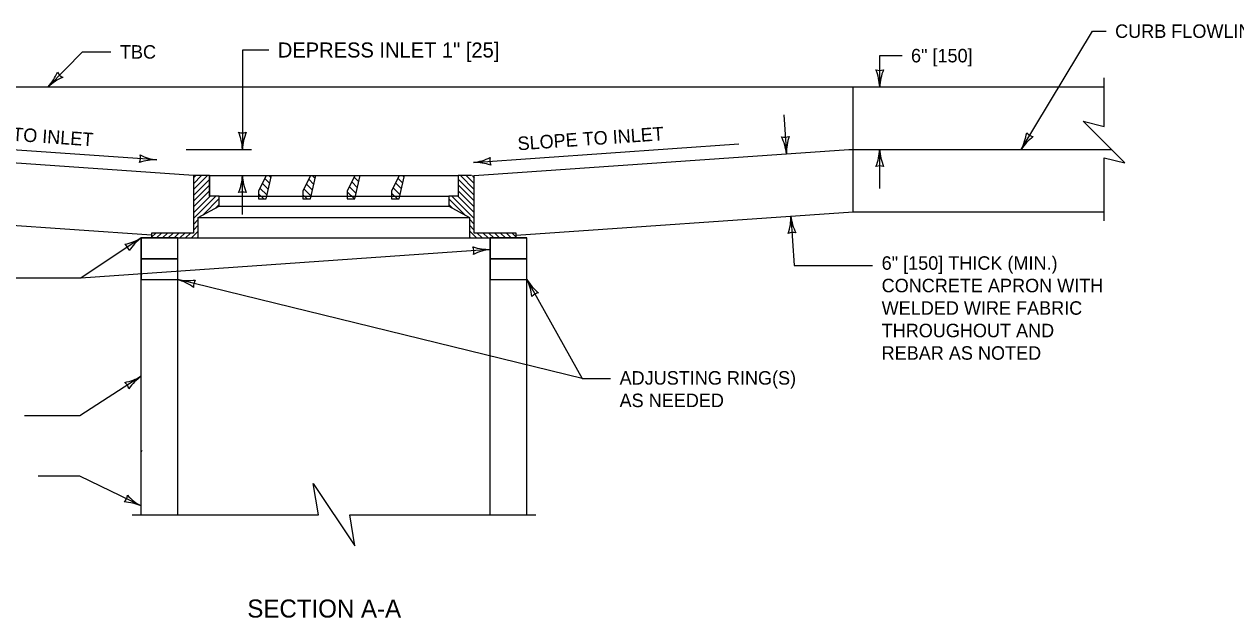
# Model space of a CAD drawing. Extents: x 49991.4 to 50048.3, y 49987.6 to 50018.3.
# Drawn here: x 50007.22 to 50012.6, y 49991.19 to 49993.83 of the extents above; entities that cross this region are included whole.
import ezdxf

# ---------------------------------------------------------------- set-up
doc = ezdxf.new("R2010")
doc.units = 0
for name, color, linetype in [('Level 1', 7, 'Continuous'), ('Level 2', 7, 'Continuous'), ('Level 3', 7, 'Continuous'), ('Level 4', 7, 'Continuous'), ('Level 6', 7, 'Continuous')]:
    doc.layers.add(name, color=color, linetype=linetype)

msp = doc.modelspace()

# ---------------------------------------------------------------- linework, layer by layer
at = {"layer": 'Level 1'}
for p, q in [((50006.2842, 49993.5547), (50010.9017, 49993.5547)), ((50010.9017, 49993.5547), (50012.0159, 49993.5547)), ((50010.9017, 49992.9997), (50010.9017, 49993.5547)), ((50007.9687, 49993.1608), (50006.3036, 49993.2772)), ((50009.2173, 49993.1608), (50010.8823, 49993.2772)), ((50010.8823, 49993.2772), (50012.048, 49993.2772)), ((50008.0399, 49993.1608), (50007.9687, 49993.1608)), ((50007.9687, 49993.1608), (50007.9687, 49992.9052)), ((50007.9687, 49993.1501), (50007.9794, 49993.1608)), ((50007.9687, 49993.1242), (50008.0052, 49993.1608)), ((50007.9687, 49993.0984), (50008.0311, 49993.1608)), ((50008.0399, 49993.1608), (50009.1461, 49993.1608)), ((50008.0399, 49993.1608), (50008.0399, 49993.0695)), ((50008.0399, 49993.0695), (50008.0399, 49993.1608)), ((50008.3042, 49993.1608), (50008.3137, 49993.1512)), ((50008.4965, 49993.1608), (50008.5099, 49993.1474)), ((50008.6831, 49993.1534), (50008.7037, 49993.1328)), ((50008.7075, 49993.1608), (50008.7095, 49993.1588)), ((50008.8981, 49993.1608), (50008.9054, 49993.1535)), ((50009.1461, 49993.1608), (50009.1461, 49993.0695)), ((50009.2045, 49993.1608), (50009.1461, 49993.1608)), ((50009.1461, 49993.1608), (50009.1461, 49993.0695)), ((50009.1557, 49993.1608), (50009.2173, 49993.0993)), ((50009.1815, 49993.1608), (50009.2173, 49993.1251)), ((50009.2073, 49993.1608), (50009.2173, 49993.1509)), ((50009.2173, 49992.9052), (50009.2173, 49993.1608)), ((50007.9687, 49993.0726), (50008.0399, 49993.1438)), ((50007.9687, 49993.0468), (50008.0399, 49993.118)), ((50008.2647, 49993.1048), (50008.2964, 49993.0731)), ((50008.2753, 49993.126), (50008.3022, 49993.0991)), ((50008.2859, 49993.1472), (50008.308, 49993.1252)), ((50008.4602, 49993.1017), (50008.4926, 49993.0693)), ((50008.4708, 49993.1229), (50008.4984, 49993.0953)), ((50008.4814, 49993.1441), (50008.5042, 49993.1214)), ((50008.6619, 49993.111), (50008.6922, 49993.0807)), ((50008.6725, 49993.1322), (50008.698, 49993.1067)), ((50008.8568, 49993.1066), (50008.888, 49993.0754)), ((50008.8674, 49993.1278), (50008.8938, 49993.1014)), ((50008.878, 49993.1491), (50008.8996, 49993.1274)), ((50009.1461, 49993.1446), (50009.2173, 49993.0734)), ((50009.1461, 49993.1188), (50009.2173, 49993.0476)), ((50007.9687, 49993.021), (50008.0399, 49993.0922)), ((50007.9687, 49992.9952), (50008.0431, 49993.0695)), ((50007.9687, 49992.9694), (50008.0689, 49993.0695)), ((50008.0101, 49992.9849), (50008.0837, 49993.0585)), ((50008.0837, 49993.0695), (50008.0399, 49993.0695)), ((50008.0837, 49993.0239), (50008.0837, 49993.0695)), ((50008.2579, 49993.0798), (50008.2812, 49993.0565)), ((50008.455, 49993.0751), (50008.4736, 49993.0565)), ((50008.652, 49993.089), (50008.6846, 49993.0565)), ((50008.652, 49993.0572), (50008.6528, 49993.0565)), ((50008.8491, 49993.0825), (50008.8751, 49993.0565)), ((50009.1461, 49993.0695), (50009.1041, 49993.0695)), ((50009.1041, 49993.0695), (50009.1041, 49993.0239)), ((50009.1041, 49993.0575), (50009.1772, 49992.9844)), ((50009.1179, 49993.0695), (50009.2173, 49992.9702)), ((50009.1437, 49993.0695), (50009.2173, 49992.996)), ((50009.1461, 49993.093), (50009.2173, 49993.0218)), ((50007.7825, 49992.8949), (50006.2842, 49992.9997)), ((50007.9906, 49992.9746), (50008.0837, 49993.0239)), ((50008.0649, 49993.014), (50008.0837, 49993.0327)), ((50009.1041, 49993.0317), (50009.1211, 49993.0147)), ((50009.1041, 49993.0239), (50009.1953, 49992.9746)), ((50009.4034, 49992.8949), (50010.9017, 49992.9997)), ((50010.9017, 49992.9997), (50012.0159, 49992.9997)), ((50007.9687, 49992.9435), (50007.9906, 49992.9654)), ((50007.9687, 49992.9177), (50007.9906, 49992.9396)), ((50007.9906, 49992.9746), (50009.1953, 49992.9746)), ((50007.9906, 49992.8833), (50007.9906, 49992.9746)), ((50009.1953, 49992.9746), (50009.1953, 49992.8833)), ((50009.1953, 49992.9663), (50009.2173, 49992.9444)), ((50009.1953, 49992.9405), (50009.2173, 49992.9185)), ((50007.7369, 49991.653), (50007.7369, 49992.8833)), ((50007.7369, 49992.8833), (50007.8993, 49992.8833)), ((50007.7825, 49992.9034), (50007.7843, 49992.9052)), ((50007.9687, 49992.9052), (50007.7825, 49992.9052)), ((50007.7825, 49992.9052), (50007.7825, 49992.8833)), ((50007.7825, 49992.8864), (50007.8013, 49992.9052)), ((50007.7825, 49992.8833), (50007.9906, 49992.8833)), ((50007.8052, 49992.8833), (50007.8271, 49992.9052)), ((50007.831, 49992.8833), (50007.853, 49992.9052)), ((50007.8569, 49992.8833), (50007.8788, 49992.9052)), ((50007.8827, 49992.8833), (50007.9046, 49992.9052)), ((50007.8993, 49991.653), (50007.8993, 49992.8833)), ((50007.9085, 49992.8833), (50007.9304, 49992.9052)), ((50007.9343, 49992.8833), (50007.9562, 49992.9052)), ((50007.9601, 49992.8833), (50007.9906, 49992.9138)), ((50007.9859, 49992.8833), (50007.9906, 49992.888)), ((50007.9906, 49992.8833), (50009.1953, 49992.8833)), ((50009.1953, 49992.9146), (50009.2267, 49992.8833)), ((50009.1953, 49992.8888), (50009.2008, 49992.8833)), ((50009.1953, 49992.8833), (50009.4034, 49992.8833)), ((50009.4034, 49992.9052), (50009.2173, 49992.9052)), ((50009.2306, 49992.9052), (50009.2525, 49992.8833)), ((50009.2564, 49992.9052), (50009.2783, 49992.8833)), ((50009.2822, 49992.9052), (50009.3041, 49992.8833)), ((50009.2884, 49992.8833), (50009.4509, 49992.8833)), ((50009.2884, 49991.653), (50009.2884, 49992.8833)), ((50009.308, 49992.9052), (50009.3299, 49992.8833)), ((50009.3338, 49992.9052), (50009.3557, 49992.8833)), ((50009.3596, 49992.9052), (50009.3815, 49992.8833)), ((50009.3855, 49992.9052), (50009.4034, 49992.8872)), ((50009.4034, 49992.8833), (50009.4034, 49992.9052)), ((50009.4509, 49991.653), (50009.4509, 49992.8833)), ((50007.7369, 49991.9305), (50007.7405, 49991.9396))]:
    msp.add_line(p, q, dxfattribs=at)
for points in [[(50008.2927, 49993.1608), (50008.2579, 49993.0912), (50008.2579, 49993.0565), (50008.2927, 49993.0565), (50008.3159, 49993.1608)], [(50008.4897, 49993.1608), (50008.455, 49993.0912), (50008.455, 49993.0565), (50008.4897, 49993.0565), (50008.5129, 49993.1608)], [(50008.6868, 49993.1608), (50008.652, 49993.0912), (50008.652, 49993.0565), (50008.6868, 49993.0565), (50008.71, 49993.1608)], [(50008.8838, 49993.1608), (50008.8491, 49993.0912), (50008.8491, 49993.0565), (50008.8838, 49993.0565), (50008.907, 49993.1608)]]:
    msp.add_lwpolyline(points, dxfattribs=at)
for points in [[(50007.8993, 49992.8833), (50007.7369, 49992.8833), (50007.7369, 49992.7906), (50007.8993, 49992.7906)], [(50009.4509, 49992.7906), (50009.4509, 49992.8833), (50009.2884, 49992.8833), (50009.2884, 49992.7906)], [(50007.8993, 49992.7906), (50007.7369, 49992.7906), (50007.7369, 49992.6979), (50007.8993, 49992.6979)], [(50009.4509, 49992.6979), (50009.4509, 49992.7906), (50009.2884, 49992.7906), (50009.2884, 49992.6979)]]:
    msp.add_lwpolyline(points, close=True, dxfattribs=at)
at = {"layer": 'Level 3'}
for p, q in [((50011.6473, 49993.2772), (50011.9651, 49993.8026)), ((50011.9651, 49993.8026), (50012.0253, 49993.8026)), ((50007.3229, 49993.5547), (50007.4753, 49993.7104)), ((50008.304, 49993.7188), (50008.1865, 49993.7188)), ((50008.1865, 49993.7187), (50008.1865, 49993.2772)), ((50011.019, 49993.5547), (50011.019, 49993.6938)), ((50010.5927, 49993.4308), (50010.6048, 49993.2578)), ((50007.8062, 49993.2303), (50006.7304, 49993.3055)), ((50007.9363, 49993.2772), (50008.2265, 49993.2772)), ((50009.2132, 49993.2186), (50010.3931, 49993.3011)), ((50011.019, 49993.1038), (50011.019, 49993.2772)), ((50008.1865, 49992.9874), (50008.1865, 49993.1608)), ((50010.6242, 49992.9803), (50010.6395, 49992.7613)), ((50007.7369, 49992.8833), (50007.468, 49992.7051)), ((50009.2884, 49992.8323), (50007.468, 49992.7051)), ((50010.6395, 49992.7613), (50010.9876, 49992.7613)), ((50007.468, 49992.7051), (50006.8881, 49992.7051)), ((50009.696, 49992.2578), (50007.8993, 49992.6979)), ((50009.4509, 49992.6979), (50009.696, 49992.2578)), ((50007.7369, 49992.2682), (50007.4635, 49992.0926)), ((50009.696, 49992.2578), (50009.8229, 49992.2578)), ((50007.4635, 49992.0926), (50007.2186, 49992.0926)), ((50007.4635, 49991.824), (50007.2786, 49991.824)), ((50007.7369, 49991.6916), (50007.4635, 49991.824))]:
    msp.add_line(p, q, dxfattribs=at)
for points in [[(50007.4753, 49993.7104), (50007.6022, 49993.7104), (50007.6022, 49993.7104)], [(50011.019, 49993.6938), (50011.1181, 49993.6938), (50011.1181, 49993.6938)]]:
    msp.add_lwpolyline(points, dxfattribs=at)
for centre, radius, start, end in [((50007.1486, 49993.7093), 0.233, 318.4551, 337.705), ((50007.4753, 49993.3928), 0.2223, 113.0838, 133.2673), ((50007.4126, 49993.6464), 0.0548, 207.7666, 243.489), ((50011.019, 49993.6829), 0.0548, 252.1388, 287.8612), ((50010.7863, 49993.5432), 0.233, 2.8273, 22.0772), ((50011.2411, 49993.5456), 0.2223, 157.456, 177.6395), ((50008.1865, 49993.4054), 0.0548, 252.1388, 287.8612), ((50007.9538, 49993.2657), 0.233, 2.8273, 22.0772), ((50008.4086, 49993.2681), 0.2223, 157.456, 177.6395), ((50010.5959, 49993.3857), 0.0548, 256.1388, 291.8612), ((50010.3735, 49993.2301), 0.233, 6.8273, 26.0772), ((50010.827, 49993.2642), 0.2223, 161.456, 181.6395), ((50011.4423, 49993.3878), 0.233, 331.6545, 350.9044), ((50011.8326, 49993.1544), 0.2223, 126.2832, 146.4667), ((50011.7137, 49993.3869), 0.0548, 220.966, 256.6884), ((50010.7968, 49993.2864), 0.2223, 337.456, 357.6395), ((50011.2517, 49993.2887), 0.233, 182.8273, 202.0772), ((50007.6783, 49993.2392), 0.0548, 338.1388, 13.8612), ((50007.8014, 49992.9973), 0.233, 88.8273, 108.0772), ((50007.8308, 49993.4512), 0.2223, 243.456, 263.6395), ((50009.1855, 49993.45), 0.233, 276.8273, 296.0772), ((50009.2196, 49992.9964), 0.2223, 71.456, 91.6395), ((50009.3411, 49993.2276), 0.0548, 166.1388, 201.8612), ((50007.9644, 49993.1699), 0.2223, 337.456, 357.6395), ((50008.4192, 49993.1723), 0.233, 182.8273, 202.0772), ((50011.019, 49993.149), 0.0548, 72.1388, 107.8612), ((50008.1865, 49993.0326), 0.0548, 72.1388, 107.8612), ((50010.402, 49992.9739), 0.2223, 341.456, 1.6395), ((50010.8556, 49993.008), 0.233, 186.8273, 206.0772), ((50007.6217, 49993.0735), 0.2223, 281.0074, 301.1909), ((50007.8751, 49992.6957), 0.233, 126.3787, 145.6286), ((50010.6332, 49992.8524), 0.0548, 76.1388, 111.8612), ((50007.63, 49992.8125), 0.0548, 15.6902, 51.4126), ((50009.2821, 49993.0546), 0.2223, 251.455, 271.6385), ((50009.1605, 49992.8234), 0.0548, 346.1378, 21.8601), ((50009.3161, 49992.601), 0.233, 96.8263, 116.0761), ((50007.8376, 49992.4843), 0.2223, 53.6917, 73.8752), ((50007.9435, 49992.9266), 0.233, 259.063, 278.3129), ((50008.0239, 49992.6674), 0.0548, 148.3745, 184.0969), ((50009.2524, 49992.5978), 0.2223, 6.5659, 26.7494), ((50009.6486, 49992.8211), 0.233, 211.9372, 231.187), ((50009.5133, 49992.5859), 0.0548, 101.2487, 136.9711), ((50007.6245, 49992.46), 0.2223, 280.1784, 300.3619), ((50007.629, 49992.1989), 0.0548, 14.8612, 50.5835), ((50007.8723, 49992.0786), 0.233, 125.5497, 144.7995), ((50007.6215, 49991.7475), 0.0548, 316.304, 352.0263), ((50007.6458, 49991.4772), 0.233, 66.9924, 86.2423), ((50007.8419, 49991.8876), 0.2223, 221.6211, 241.8047)]:
    msp.add_arc(centre, radius, start, end, dxfattribs=at)
at = {"layer": 'Level 4'}
for p, q in [((50008.0837, 49993.0695), (50009.1041, 49993.0695)), ((50008.0837, 49993.0239), (50009.1041, 49993.0239))]:
    msp.add_line(p, q, dxfattribs=at)
at = {"layer": 'Level 6'}
for points in [[(50012.0159, 49992.9597), (50012.0159, 49993.2398), (50012.1086, 49993.2166), (50011.9232, 49993.4021), (50012.0159, 49993.3789), (50012.0159, 49993.5947)], [(50007.6969, 49991.653), (50008.5243, 49991.653), (50008.5012, 49991.7921), (50008.6866, 49991.5139), (50008.6634, 49991.653), (50009.4909, 49991.653)]]:
    msp.add_lwpolyline(points, dxfattribs=at)

# ---------------------------------------------------------------- texts
at = {"layer": 'Level 2'}
for s, height, p in [('CURB FLOWLINE', 0.06, (50012.0653, 49993.7726)), ('DEPRESS INLET 1" [25]', 0.066765, (50008.344, 49993.6855)), ('TBC', 0.06, (50007.6422, 49993.6804)), ('6" [150]', 0.06, (50011.1581, 49993.6638)), ('6" [150] THICK (MIN.)', 0.06, (50011.0276, 49992.7418)), ('CONCRETE APRON WITH ', 0.06, (50011.0276, 49992.6418)), ('WELDED WIRE FABRIC ', 0.06, (50011.0276, 49992.5418)), ('THROUGHOUT AND', 0.06, (50011.0276, 49992.4418)), ('REBAR AS NOTED', 0.06, (50011.0276, 49992.3418)), ('ADJUSTING RING(S)', 0.06, (50009.8629, 49992.2311)), ('AS NEEDED', 0.06, (50009.8629, 49992.1311)), ('SECTION A-A', 0.08, (50008.2083, 49991.1957))]:
    msp.add_text(s, height=height, dxfattribs=at).set_placement(p)
for rotation, p in [(356, (50006.8726, 49993.3356)), (4, (50009.4116, 49993.2726))]:
    msp.add_text('SLOPE TO INLET', height=0.06, rotation=rotation, dxfattribs=at).set_placement(p)

doc.saveas('drawing.dxf')
